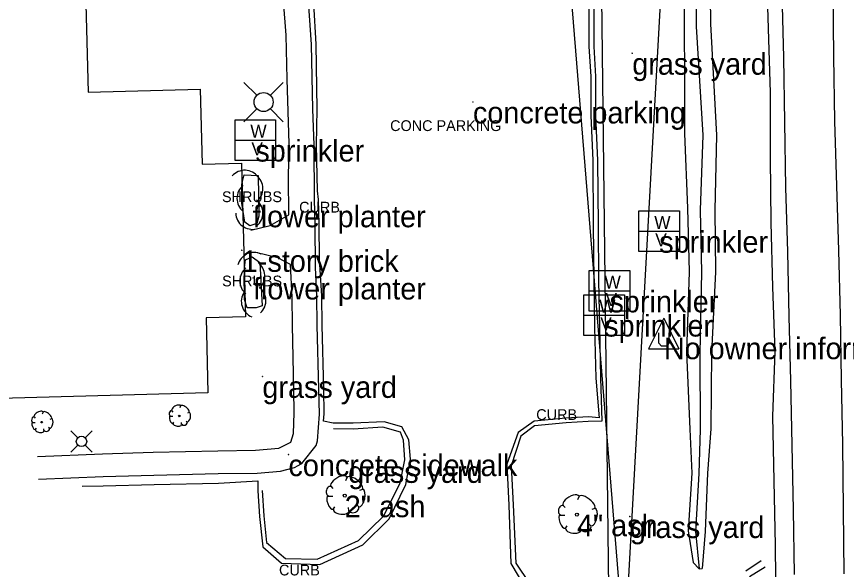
# Model space of a CAD drawing. Extents: x 1802180 to 1804859, y 572524 to 575172.
# Drawn here: x 1803337 to 1803529.6, y 574468.6 to 574596.9 of the extents above; entities that cross this region are included whole.
import ezdxf

# ---------------------------------------------------------------- set-up
doc = ezdxf.new("R2010")
doc.units = 0
for name, color, linetype in [('EX_EDGE_PAVEMENT', 7, 'Continuous'), ('EX_SHOULDER', 7, 'Continuous'), ('S_BASELINE', 7, 'Continuous'), ('S_BUILDING', 7, 'Continuous'), ('S_CURB', 7, 'Continuous'), ('S_CURB_ANNOT', 7, 'Continuous'), ('S_DITCHLINE', 7, 'Continuous'), ('S_MSC_PT_SYM', 7, 'Continuous'), ('S_PARKING', 7, 'Continuous'), ('S_PARKING_ANNOT', 7, 'Continuous'), ('S_PAVEMENT_CROWN', 7, 'Continuous'), ('S_SANITARY_SEWER', 7, 'Continuous'), ('S_SIDEWALK', 7, 'Continuous'), ('S_SURVEY_TEXT_ANNOT', 7, 'Continuous'), ('S_TREE', 7, 'Continuous'), ('S_TREE_ANNOT', 7, 'Continuous'), ('S_UTILITY_POLE', 7, 'Continuous'), ('S_UTILITY_POLE_ANNOT', 7, 'Continuous'), ('S_WATER_UTILITIES', 7, 'Continuous'), ('S_WATER_UTILITIES_ANNOT', 7, 'Continuous')]:
    doc.layers.add(name, color=color, linetype=linetype)

msp = doc.modelspace()

# ---------------------------------------------------------------- linework, layer by layer
at = {"layer": 'EX_EDGE_PAVEMENT'}
msp.add_lwpolyline([(1803511.15, 574752.25), (1803511.51, 574737.25), (1803511.85, 574722.28), (1803512.06, 574707.28), (1803512.41, 574692.1), (1803512.98, 574677.21), (1803513.44, 574662.21), (1803513.59, 574647.61), (1803513.85, 574632.28), (1803514.23, 574617.28), (1803514.59, 574602.41), (1803515.02, 574587.41), (1803515.25, 574572.41), (1803515.5, 574557.21), (1803515.92, 574542.31), (1803516.28, 574527.32), (1803516.63, 574512.39), (1803516.94, 574497.47), (1803517.26, 574482.47), (1803517.51, 574467.47)], dxfattribs=at)
at = {"layer": 'EX_SHOULDER'}
msp.add_lwpolyline([(1803513.3, 574459.21), (1803513.14, 574474.16), (1803512.83, 574489.15), (1803512.51, 574504.15), (1803513.08, 574519.16), (1803512.55, 574534.14), (1803512.14, 574549.14), (1803512, 574564.12), (1803511.96, 574579.17), (1803511.52, 574594.12), (1803511.07, 574609.12), (1803510.69, 574624.12), (1803510.14, 574639.14), (1803510.02, 574654.22), (1803509.58, 574669.09), (1803508.98, 574684.03), (1803508.41, 574699.09), (1803508.62, 574714.13), (1803508.42, 574729.1), (1803508.04, 574744.09), (1803507.71, 574759.1)], dxfattribs=at)
at = {"layer": 'S_BASELINE'}
msp.add_line((1803445.92, 573868.28), (1803500.45, 574852.59), dxfattribs=at)
at = {"layer": 'S_BUILDING'}
msp.add_lwpolyline([(1803352.38, 574626.19), (1803353.61, 574579.37), (1803379.63, 574580.05), (1803380.08, 574562.6), (1803389.19, 574562.84), (1803390.13, 574527.22), (1803380.96, 574526.98), (1803381.42, 574509.56), (1803327.48, 574508.15)], dxfattribs=at)
at = {"layer": 'S_CURB'}
for points in [[(1803470.96, 574599.35), (1803470.98, 574589.91), (1803471.4, 574583), (1803471.38, 574573.95), (1803471.85, 574563.51), (1803471.97, 574548.47), (1803472.09, 574535.65), (1803472.28, 574524.77), (1803472.57, 574513.04), (1803472.82, 574503), (1803469.64, 574502.97), (1803464.55, 574502.65), (1803457.22, 574501.92), (1803454.03, 574499.53), (1803451.81, 574492.66), (1803452.28, 574483.6), (1803452.89, 574470.07), (1803456.02, 574465.38)], [(1803394.02, 574486.94), (1803394.38, 574481.05), (1803395.01, 574474.89), (1803399.42, 574471.16), (1803406.79, 574471), (1803416.36, 574475.38), (1803422.13, 574481.01), (1803426, 574488.62), (1803427.11, 574494.09), (1803426.82, 574498.64), (1803426.11, 574500.46), (1803421.99, 574501.63), (1803415.14, 574501.14), (1803410.52, 574501.25)], [(1803506.27, 574468.32), (1803509.83, 574470.7)]]:
    msp.add_lwpolyline(points, dxfattribs=at)
at = {"layer": 'S_DITCHLINE'}
for points in [[(1803490.07, 574794.16), (1803489.66, 574780.03), (1803490.7, 574755.99), (1803491.27, 574742.62), (1803491.83, 574729.26), (1803492.65, 574716.19), (1803493.48, 574703.12), (1803493.27, 574678.93), (1803493.61, 574663.96), (1803493.94, 574648.99), (1803494.34, 574635.02), (1803494.73, 574621.05), (1803494.72, 574607.79), (1803494.71, 574594.54), (1803495.49, 574581.95), (1803496.28, 574569.36), (1803495.67, 574551.97), (1803495.95, 574537.6), (1803495.58, 574518.76), (1803495.69, 574501.1), (1803495.36, 574490.9), (1803494.55, 574477.41), (1803495.42, 574468.77), (1803496.15, 574468.87)], [(1803490.07, 574794.16), (1803491.29, 574793.32), (1803491.77, 574780.2), (1803493.77, 574756.45), (1803494.07, 574742.95), (1803494.36, 574729.45), (1803495.37, 574716.3), (1803496.38, 574703.14), (1803496.39, 574679.47), (1803496.92, 574664.43), (1803497.45, 574649.38), (1803497.65, 574635.15), (1803497.85, 574620.92), (1803497.95, 574608.06), (1803498.05, 574595.2), (1803498.74, 574582.27), (1803499.43, 574569.34), (1803499.04, 574551.94), (1803499.25, 574537.64), (1803498.31, 574518.86), (1803498.17, 574501.26), (1803497.39, 574490.99), (1803496.83, 574477.44), (1803496.15, 574468.87)], [(1803487.53, 574756.11), (1803488.21, 574742.54), (1803488.9, 574728.98), (1803489.77, 574715.83), (1803490.65, 574702.69), (1803490.32, 574678.88), (1803490.92, 574663.88), (1803491.52, 574648.88), (1803491.74, 574634.91), (1803491.96, 574620.93), (1803491.97, 574607.92), (1803491.99, 574594.91), (1803492.03, 574582.33), (1803492.07, 574569.76), (1803492.72, 574552.46), (1803493.14, 574537.68), (1803492.47, 574519.03), (1803493.27, 574501.14), (1803493.74, 574490.94), (1803492.85, 574477.56), (1803494.06, 574470.25), (1803495.42, 574468.77)]]:
    msp.add_lwpolyline(points, dxfattribs=at)
at = {"layer": 'S_MSC_PT_SYM'}
for points in [[(1803479.91, 574588.39), (1803479.91, 574588.44), (1803479.91, 574588.39), (1803479.86, 574588.39), (1803479.91, 574588.39), (1803479.91, 574588.34), (1803479.91, 574588.39), (1803479.96, 574588.39)], [(1803442.92, 574577.08), (1803442.92, 574577.13), (1803442.92, 574577.08), (1803442.87, 574577.08), (1803442.92, 574577.08), (1803442.92, 574577.03), (1803442.92, 574577.08), (1803442.97, 574577.08)], [(1803391.81, 574553), (1803391.81, 574553.05), (1803391.81, 574553), (1803391.76, 574553), (1803391.81, 574553), (1803391.81, 574552.95), (1803391.81, 574553), (1803391.86, 574553)], [(1803389.27, 574542.66), (1803389.27, 574542.71), (1803389.27, 574542.66), (1803389.22, 574542.66), (1803389.27, 574542.66), (1803389.27, 574542.61), (1803389.27, 574542.66), (1803389.32, 574542.66)], [(1803391.87, 574536.25), (1803391.87, 574536.3), (1803391.87, 574536.25), (1803391.82, 574536.25), (1803391.87, 574536.25), (1803391.87, 574536.2), (1803391.87, 574536.25), (1803391.92, 574536.25)], [(1803394.05, 574513.42), (1803394.05, 574513.47), (1803394.05, 574513.42), (1803394, 574513.42), (1803394.05, 574513.42), (1803394.05, 574513.37), (1803394.05, 574513.42), (1803394.1, 574513.42)], [(1803400.1, 574495.27), (1803400.1, 574495.32), (1803400.1, 574495.27), (1803400.05, 574495.27), (1803400.1, 574495.27), (1803400.1, 574495.22), (1803400.1, 574495.27), (1803400.15, 574495.27)], [(1803413.97, 574493.71), (1803413.97, 574493.76), (1803413.97, 574493.71), (1803413.92, 574493.71), (1803413.97, 574493.71), (1803413.97, 574493.66), (1803413.97, 574493.71), (1803414.02, 574493.71)], [(1803479.35, 574480.92), (1803479.35, 574480.97), (1803479.35, 574480.92), (1803479.3, 574480.92), (1803479.35, 574480.92), (1803479.35, 574480.87), (1803479.35, 574480.92), (1803479.4, 574480.92)]]:
    msp.add_lwpolyline(points, dxfattribs=at)
at = {"layer": 'S_PARKING'}
for points in [[(1803352.19, 574487.93), (1803357.12, 574487.99), (1803368.9, 574488.32), (1803383.83, 574488.64), (1803393.02, 574489.15), (1803393.01, 574486.89), (1803393.37, 574480.95), (1803394.15, 574473.9), (1803398.51, 574470.11), (1803407.35, 574469.76), (1803417.4, 574474.34), (1803423.45, 574480.37), (1803427.31, 574488.37), (1803428.42, 574494.2), (1803428.01, 574498.73), (1803426.45, 574501.73), (1803422.33, 574502.9), (1803415.13, 574502.54), (1803410.51, 574502.55), (1803408.23, 574503.05), (1803408.42, 574504.69), (1803408.3, 574510.44), (1803407.91, 574525.31), (1803407.86, 574532.13), (1803407.32, 574540.63), (1803407.26, 574548.69), (1803407.07, 574554.44), (1803406.83, 574556.44), (1803406.6, 574567.05), (1803406.77, 574575.38), (1803406.56, 574590.45), (1803405.98, 574599.88)], [(1803406.83, 574556.44), (1803406.6, 574567.05), (1803406.77, 574575.38), (1803406.56, 574590.45), (1803405.98, 574599.88)], [(1803469.84, 574599.34), (1803469.86, 574589.91), (1803470.29, 574582.94), (1803470.27, 574573.95), (1803470.73, 574563.46), (1803470.85, 574548.46), (1803470.97, 574535.63), (1803471.16, 574524.75), (1803471.46, 574513.01), (1803472.26, 574503.83), (1803469.72, 574504.05), (1803464.48, 574503.75), (1803457.11, 574503), (1803453.4, 574500.41), (1803450.79, 574493.02), (1803451.23, 574483.55), (1803451.72, 574470.03), (1803454.9, 574464.7)], [(1803469.84, 574599.34), (1803469.86, 574589.91), (1803470.29, 574582.94), (1803470.27, 574573.95), (1803470.73, 574563.46), (1803470.85, 574548.46), (1803470.97, 574535.63), (1803471.16, 574524.75), (1803471.46, 574513.01), (1803472.26, 574503.83), (1803469.72, 574504.05), (1803464.48, 574503.75), (1803457.11, 574503), (1803453.4, 574500.41), (1803450.79, 574493.02), (1803451.23, 574483.55), (1803451.72, 574470.03), (1803454.9, 574464.7)], [(1803407.32, 574540.63), (1803407.26, 574548.69), (1803407.07, 574554.44), (1803406.83, 574556.44)], [(1803410.51, 574502.55), (1803408.23, 574503.05), (1803408.42, 574504.69), (1803408.3, 574510.44), (1803407.91, 574525.31), (1803407.86, 574532.13), (1803407.32, 574540.63)], [(1803393.01, 574486.89), (1803393.37, 574480.95), (1803394.15, 574473.9), (1803398.51, 574470.11), (1803407.35, 574469.76), (1803417.4, 574474.34), (1803423.45, 574480.37), (1803427.31, 574488.37), (1803428.42, 574494.2), (1803428.01, 574498.73), (1803426.45, 574501.73), (1803422.33, 574502.9), (1803415.13, 574502.54), (1803410.51, 574502.55)], [(1803352.19, 574487.93), (1803357.12, 574487.99), (1803368.9, 574488.32), (1803383.83, 574488.64), (1803393.02, 574489.15), (1803393.01, 574486.89)], [(1803507.13, 574466.99), (1803510.75, 574469.2)], [(1803507.13, 574466.99), (1803510.75, 574469.2)]]:
    msp.add_lwpolyline(points, dxfattribs=at)
at = {"layer": 'S_PAVEMENT_CROWN'}
msp.add_lwpolyline([(1803522.78, 574752.53), (1803523.15, 574737.54), (1803523.48, 574722.54), (1803523.82, 574707.54), (1803524.16, 574692.55), (1803524.71, 574677.56), (1803525.16, 574662.57), (1803525.35, 574647.57), (1803525.71, 574632.58), (1803526.09, 574617.58), (1803526.43, 574602.58), (1803526.65, 574587.59), (1803526.88, 574572.59), (1803527.34, 574557.6), (1803527.76, 574542.6), (1803528.13, 574527.61), (1803528.41, 574512.61), (1803528.68, 574497.61), (1803528.87, 574482.61), (1803529.05, 574467.61)], dxfattribs=at)
at = {"layer": 'S_SANITARY_SEWER'}
msp.add_line((1803476.11, 574323.57), (1803471.91, 574684.3), dxfattribs=at)
at = {"layer": 'S_SIDEWALK'}
for points in [[(1803406.12, 574554.41), (1803406.06, 574567.03), (1803405.78, 574575.37), (1803405.48, 574590.37), (1803404.61, 574602.79), (1803402.97, 574611.64), (1803395.75, 574624.79), (1803394.04, 574627.85), (1803389.23, 574639.39), (1803388.7, 574640.8), (1803387.42, 574645.41), (1803387.79, 574671.38), (1803389.48, 574678.51), (1803394.14, 574690.07), (1803398, 574696.26), (1803400.4, 574701.13), (1803401.4, 574704.86), (1803402.06, 574713.11), (1803402.01, 574720.64), (1803401.84, 574733.16), (1803401.24, 574742.39), (1803401.18, 574749.16), (1803400.93, 574758.59)], [(1803391.4, 574547.3), (1803395.83, 574548.38), (1803400.2, 574550.92), (1803400.12, 574559.56), (1803400.25, 574567.33), (1803399.8, 574582.33), (1803399.55, 574592.57), (1803398.4, 574607.57)], [(1803406.39, 574538.67), (1803406.31, 574548.67), (1803406.12, 574554.41)], [(1803341.88, 574494.8), (1803356.9, 574495.45), (1803368.73, 574495.83), (1803383.72, 574496.17), (1803392.44, 574496.29), (1803397.86, 574496.73), (1803400.63, 574498.19), (1803401.26, 574500.2), (1803401.46, 574504.92), (1803401.38, 574510.27), (1803401.01, 574525.27), (1803400.97, 574531.8), (1803400.61, 574539.4), (1803397.67, 574540.92), (1803392.8, 574542.08)], [(1803342.11, 574489.61), (1803357.06, 574490.21), (1803368.85, 574490.53), (1803383.79, 574490.87), (1803392.87, 574491), (1803398.29, 574491.43), (1803401.47, 574492.31), (1803403.24, 574493.24), (1803406.51, 574497.4), (1803406.81, 574498.46), (1803407.28, 574504.67), (1803407.15, 574510.41), (1803406.76, 574525.31), (1803406.71, 574532.07), (1803406.39, 574538.67)]]:
    msp.add_lwpolyline(points, dxfattribs=at)
at = {"layer": 'S_TREE'}
for p, q in [((1803375.07, 574506.59), (1803374.86, 574506.11)), ((1803341.04, 574504.02), (1803341.32, 574503.7)), ((1803343.14, 574505.13), (1803342.92, 574504.66)), ((1803372.61, 574504.19), (1803373.23, 574504.19)), ((1803372.98, 574505.47), (1803373.25, 574505.15)), ((1803377.04, 574505.05), (1803376.67, 574504.9)), ((1803340.68, 574502.74), (1803341.3, 574502.74)), ((1803345.1, 574503.59), (1803344.74, 574503.44)), ((1803373.25, 574502.44), (1803373.51, 574502.82)), ((1803375.28, 574502.29), (1803375.24, 574502.72)), ((1803376.61, 574502.78), (1803376.35, 574503.02)), ((1803341.32, 574500.98), (1803341.58, 574501.37)), ((1803343.35, 574500.83), (1803343.31, 574501.26)), ((1803344.68, 574501.33), (1803344.42, 574501.56)), ((1803413.72, 574490), (1803413.33, 574489.15)), ((1803409.92, 574487.98), (1803410.42, 574487.4)), ((1803417.28, 574487.21), (1803416.62, 574486.94)), ((1803409.26, 574485.66), (1803410.38, 574485.66)), ((1803467.61, 574485.59), (1803467.22, 574484.74)), ((1803410.42, 574482.48), (1803410.89, 574483.18)), ((1803414.1, 574482.21), (1803414.03, 574482.98)), ((1803416.51, 574483.1), (1803416.04, 574483.53)), ((1803463.81, 574483.57), (1803464.32, 574482.99)), ((1803471.18, 574482.8), (1803470.52, 574482.53)), ((1803463.16, 574481.25), (1803464.28, 574481.25)), ((1803470.4, 574478.69), (1803469.94, 574479.12)), ((1803464.32, 574478.07), (1803464.78, 574478.77)), ((1803468, 574477.8), (1803467.92, 574478.57))]:
    msp.add_line(p, q, dxfattribs=at)
for points in [[(1803393.08, 574560.02), (1803393.19, 574550.61), (1803392.76, 574548.88), (1803391.1, 574548.33), (1803389.94, 574549.2), (1803389.24, 574553.58), (1803389.25, 574558.03), (1803389.82, 574560.14), (1803393.08, 574560.02)], [(1803393.42, 574539.84), (1803393.98, 574529.79), (1803392.62, 574529.31), (1803390.55, 574529.3), (1803389.93, 574531.26), (1803389.88, 574533.88), (1803389.89, 574538.64), (1803390.15, 574540.47), (1803391.65, 574541.16), (1803393.42, 574539.84)]]:
    msp.add_lwpolyline(points, dxfattribs=at)
for centre, radius in [((1803374.76, 574504.24), 0.188), ((1803342.83, 574502.79), 0.188), ((1803413.16, 574485.75), 0.341), ((1803467.05, 574481.34), 0.341)]:
    msp.add_circle(centre, radius, dxfattribs=at)
for centre, radius, start, end in [((1803389.97, 574557.34), 3.88, 37.1078, 138.7047), ((1803390.28, 574556.98), 3.88, 309.9074, 51.5043), ((1803392.03, 574554.68), 3.88, 129.0563, 230.6533), ((1803390.28, 574551.31), 3.88, 309.9074, 51.5043), ((1803391.73, 574551.4), 3.88, 182.0883, 283.6852), ((1803392.09, 574538.29), 3.87, 63.9377, 165.5346), ((1803390.76, 574536.69), 3.87, 312.3947, 53.9916), ((1803392.68, 574535.55), 3.87, 129.0845, 230.6814), ((1803393.03, 574530.83), 3.87, 146.7352, 248.3321), ((1803391, 574531.02), 3.87, 312.3947, 53.9916)]:
    msp.add_arc(centre, radius, start, end, dxfattribs=at)
for centre, major_axis, ratio, start_param, end_param in [((1803374.03, 574506.01), (1.02, 0.6), 0.471018, 0, 3.141593), ((1803376.04, 574505.83), (-1, 0.75), 0.405113, 3.141593, 6.283186), ((1803340.86, 574503.39), (0.168, 0.567), 0.646762, 0, 3.141593), ((1803342.09, 574504.56), (1.02, 0.6), 0.471018, 0, 3.141593), ((1803344.11, 574504.38), (-1, 0.75), 0.405113, 3.141593, 6.283186), ((1803372.79, 574504.84), (0.168, 0.567), 0.646762, 0, 3.141593), ((1803372.96, 574503.38), (-0.337, 0.88), 0.420543, 6.283185, 9.424777), ((1803376.79, 574503.95), (0.25, 1.13), 0.482994, 3.141593, 6.283185), ((1803341.03, 574501.93), (-0.337, 0.88), 0.420543, 6.283185, 9.424777), ((1803344.86, 574502.5), (0.25, 1.13), 0.482994, 3.141593, 6.283185), ((1803374.32, 574502.4), (-1.01, 0.11), 0.529943, 0, 3.141593), ((1803375.95, 574502.56), (0.602, 0.255), 0.711534, 3.141592, 6.283185), ((1803342.39, 574500.94), (-1.01, 0.11), 0.529943, 0, 3.141593), ((1803344.02, 574501.11), (0.602, 0.255), 0.711534, 3.141592, 6.283185), ((1803411.82, 574488.96), (1.86, 1.08), 0.471018, 0, 3.141593), ((1803415.48, 574488.63), (-1.81, 1.36), 0.405113, 3.141593, 6.283186), ((1803409.59, 574486.84), (0.31, 1.03), 0.646762, 0, 3.141593), ((1803416.83, 574485.22), (0.46, 2.04), 0.482994, 3.141593, 6.283185), ((1803409.89, 574484.19), (-0.61, 1.6), 0.420543, 6.283185, 9.424777), ((1803465.72, 574484.55), (1.86, 1.08), 0.471018, 0, 3.141593), ((1803469.37, 574484.22), (-1.81, 1.36), 0.405113, 3.141593, 6.283186), ((1803415.31, 574482.7), (1.09, 0.46), 0.711534, 3.141592, 6.283185), ((1803463.48, 574482.43), (0.31, 1.03), 0.646762, 0, 3.141593), ((1803470.73, 574480.81), (0.46, 2.04), 0.482994, 3.141593, 6.283185), ((1803412.35, 574482.41), (-1.83, 0.19), 0.529943, 0, 3.141593), ((1803463.79, 574479.78), (-0.61, 1.6), 0.420543, 6.283185, 9.424777), ((1803466.25, 574478), (-1.83, 0.19), 0.529943, 0, 3.141593), ((1803469.21, 574478.29), (1.09, 0.46), 0.711534, 3.141592, 6.283185)]:
    msp.add_ellipse(centre, major_axis=major_axis, ratio=ratio, start_param=start_param, end_param=end_param, dxfattribs=at)
at = {"layer": 'S_UTILITY_POLE'}
for p, q in [((1803392.73, 574578.63), (1803389.74, 574581.61)), ((1803395.91, 574578.63), (1803398.89, 574581.61)), ((1803392.73, 574575.45), (1803389.74, 574572.47)), ((1803395.91, 574575.45), (1803398.89, 574572.47)), ((1803487.24, 574526.93), (1803483.71, 574519.84)), ((1803487.24, 574526.93), (1803490.73, 574519.84)), ((1803486.04, 574521.08), (1803486.04, 574523.52)), ((1803488.4, 574523.52), (1803488.4, 574521.08)), ((1803483.71, 574519.84), (1803490.73, 574519.84)), ((1803486.66, 574520.42), (1803486.04, 574521.08)), ((1803487.86, 574520.42), (1803486.66, 574520.42)), ((1803488.4, 574521.08), (1803487.86, 574520.42)), ((1803351.19, 574499.19), (1803349.56, 574500.82)), ((1803352.93, 574499.19), (1803354.56, 574500.82)), ((1803351.19, 574497.45), (1803349.56, 574495.82)), ((1803352.93, 574497.45), (1803354.56, 574495.82))]:
    msp.add_line(p, q, dxfattribs=at)
for centre, radius in [((1803394.33, 574577.05), 2.21), ((1803352.06, 574498.33), 1.21)]:
    msp.add_circle(centre, radius, dxfattribs=at)
at = {"layer": 'S_WATER_UTILITIES'}
for p, q in [((1803481.26, 574410.73), (1803462, 574648.79)), ((1803387.7, 574572.93), (1803397.12, 574572.93)), ((1803387.7, 574563.51), (1803387.7, 574572.93)), ((1803397.12, 574572.93), (1803397.12, 574563.51)), ((1803387.7, 574568.24), (1803397.12, 574568.24)), ((1803397.12, 574563.51), (1803387.7, 574563.51)), ((1803481.46, 574551.79), (1803490.87, 574551.79)), ((1803481.46, 574542.37), (1803481.46, 574551.79)), ((1803490.87, 574551.79), (1803490.87, 574542.37)), ((1803481.46, 574547.1), (1803490.87, 574547.1)), ((1803490.87, 574542.37), (1803481.46, 574542.37)), ((1803469.91, 574537.94), (1803479.32, 574537.94)), ((1803469.91, 574528.53), (1803469.91, 574537.94)), ((1803479.32, 574537.94), (1803479.32, 574528.53)), ((1803469.91, 574533.25), (1803479.32, 574533.25)), ((1803468.68, 574532.34), (1803478.09, 574532.34)), ((1803468.68, 574522.92), (1803468.68, 574532.34)), ((1803478.09, 574532.34), (1803478.09, 574522.92)), ((1803468.68, 574527.65), (1803478.09, 574527.65)), ((1803479.32, 574528.53), (1803469.91, 574528.53)), ((1803478.09, 574522.92), (1803468.68, 574522.92))]:
    msp.add_line(p, q, dxfattribs=at)

# ---------------------------------------------------------------- texts
at = {"layer": 'S_CURB_ANNOT'}
for p in [(1803402.58, 574551.41), (1803457.62, 574503.3), (1803397.91, 574467.24)]:
    msp.add_text('CURB', height=2.5, dxfattribs=at).set_placement(p)
at = {"layer": 'S_PARKING_ANNOT'}
msp.add_text('CONC PARKING', height=2.5, dxfattribs=at).set_placement((1803423.7, 574570.32))
at = {"layer": 'S_SURVEY_TEXT_ANNOT'}
for s, p in [('grass yard ', (1803479.91, 574583.39)), ('concrete parking ', (1803442.92, 574572.08)), ('flower planter ', (1803391.81, 574548)), ('1-story brick ', (1803389.27, 574537.66)), ('flower planter ', (1803391.87, 574531.25)), ('grass yard ', (1803394.05, 574508.42)), ('concrete sidewalk ', (1803400.1, 574490.27)), ('grass yard ', (1803413.97, 574488.71)), ('grass yard ', (1803479.35, 574475.92))]:
    msp.add_text(s, height=5, dxfattribs=at).set_placement(p)
at = {"layer": 'S_TREE_ANNOT'}
for s, height, p in [('SHRUBS', 2.5, (1803384.67, 574553.83)), ('SHRUBS', 2.5, (1803384.7, 574534.29)), ('2" ash ', 5, (1803413.16, 574480.75)), ('4" ash ', 5, (1803467.05, 574476.34))]:
    msp.add_text(s, height=height, dxfattribs=at).set_placement(p)
at = {"layer": 'S_UTILITY_POLE_ANNOT'}
msp.add_text('No owner information listed', height=5, dxfattribs=at).set_placement((1803487.24, 574517.4))
at = {"layer": 'S_WATER_UTILITIES'}
for s, p in [('W', (1803391.25, 574568.77)), ('V', (1803391.49, 574564.71)), ('W', (1803485.01, 574547.63)), ('V', (1803485.24, 574543.57)), ('W', (1803473.46, 574533.79)), ('W', (1803472.23, 574528.18)), ('V', (1803473.69, 574529.72)), ('V', (1803472.47, 574524.12))]:
    msp.add_text(s, height=3, rotation=360, dxfattribs=at).set_placement(p)
at = {"layer": 'S_WATER_UTILITIES_ANNOT'}
for p in [(1803392.41, 574563.24), (1803486.16, 574542.1), (1803474.62, 574528.25), (1803473.39, 574522.65)]:
    msp.add_text('sprinkler ', height=5, dxfattribs=at).set_placement(p)

doc.saveas('drawing.dxf')
